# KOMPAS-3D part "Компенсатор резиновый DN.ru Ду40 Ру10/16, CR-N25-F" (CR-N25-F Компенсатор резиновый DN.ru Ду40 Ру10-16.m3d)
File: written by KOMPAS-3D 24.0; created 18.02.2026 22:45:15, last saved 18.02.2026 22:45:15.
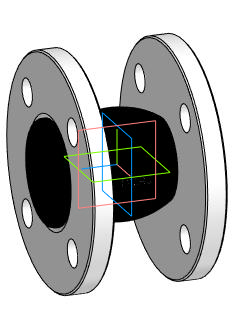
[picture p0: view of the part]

Document properties: Автор: DN.RU; Полное имя файла: D:\PROJECT CAD\DN.RU\...178(1)(ACTUALE). CR-N25-F Компенсатор резиновый DN.ru Ру10-16\DN40\CR-N25-F Компенсатор резиновый DN.ru Ду40 Ру10-16.m3d

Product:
- Body: Твердое тело2  | qty 1
    Масса: 4.436857
- Part/product: Компенсатор резиновый DN.ru Ду40 Ру10/16  | designation CR-N25-F
    Масса: 4.5
    Раздел спецификации: Прочие изделия
    Комментарий: D140-02390
    Примечание: D140-02390
    additional columns: Типовые

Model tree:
1. Твердое тело2  (labels: Твердое тело2)

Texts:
  CR-N25-F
